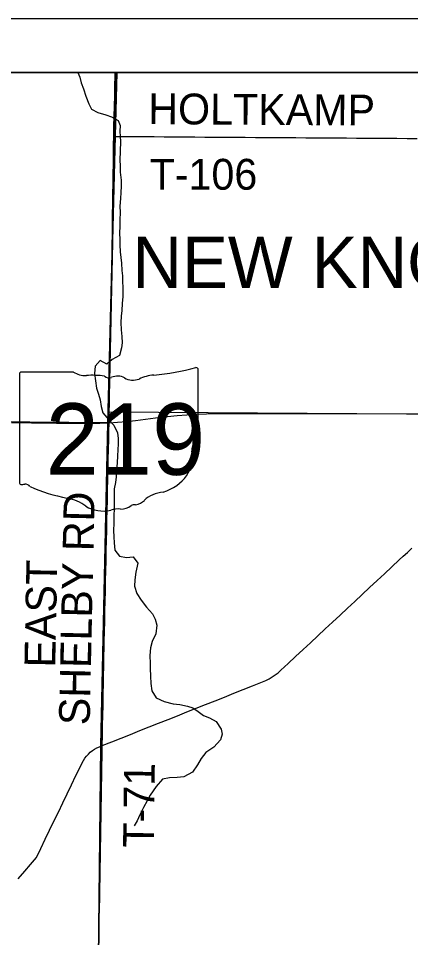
# Model space of a CAD drawing. Extents: x -11.1 to 34, y -3.9 to 22.
# Drawn here: x 7.271 to 7.994, y 19.305 to 21 of the extents above; entities that cross this region are included whole.
import ezdxf

# ---------------------------------------------------------------- set-up
doc = ezdxf.new("R2010")
doc.units = 0
for name, color, linetype in [('GM_X_Corporation', 7, 'Continuous'), ('GM_X_Corporation_Text', 7, 'Continuous'), ('GM_X_County_Road', 7, 'Continuous'), ('GM_X_Minor_River', 7, 'Continuous'), ('GM_X_State_Location', 7, 'Continuous'), ('GM_X_State_Route', 7, 'Continuous'), ('GM_X_State_Shield', 7, 'Continuous'), ('GM_X_Township_Road', 7, 'Continuous'), ('GM_X_Township_Road_Text', 7, 'Continuous'), ('SH_Data', 7, 'Continuous')]:
    doc.layers.add(name, color=color, linetype=linetype)

msp = doc.modelspace()

# ---------------------------------------------------------------- linework, layer by layer
at = {"layer": 'GM_X_Corporation'}
for points in [[(8.9, 19.2515), (8.9, 20.9), (2.1, 20.9)], [(7.4185, 19.2665), (7.4229, 19.6584), (7.436, 20.2539), (7.4494, 20.7828), (7.452, 20.9), (2.1, 20.9)], [(8.9, 19.2515), (8.9, 20.9), (7.452, 20.9), (7.4494, 20.7828), (7.436, 20.2539), (7.4229, 19.6584), (7.4185, 19.2665)]]:
    msp.add_lwpolyline(points, dxfattribs=at)
for points in [[(7.4509, 20.9), (6.4389, 20.9), (6.4249, 20.2637), (7.4361, 20.2547), (7.4373, 20.2744)], [(8.6363, 20.9), (7.4509, 20.9), (7.4373, 20.2744), (8.6259, 20.2667)]]:
    msp.add_lwpolyline(points, close=True, dxfattribs=at)
at = {"layer": 'GM_X_County_Road'}
for points in [[(7.4255, 19.659), (7.4428, 19.6659), (7.4601, 19.6728), (7.4774, 19.6797), (7.4947, 19.6866), (7.5121, 19.6935), (7.5294, 19.7004), (7.5467, 19.7073), (7.564, 19.7141), (7.5813, 19.721), (7.5987, 19.7279), (7.616, 19.7348), (7.6333, 19.7417), (7.6506, 19.7486), (7.6679, 19.7555), (7.6852, 19.7624), (7.7026, 19.7693), (7.7117, 19.7729), (7.7208, 19.7765), (7.7269, 19.7792), (7.7329, 19.7823), (7.7387, 19.7857), (7.7442, 19.7894), (7.7495, 19.7935), (7.7546, 19.798), (7.7682, 19.8107), (7.7819, 19.8234), (7.7955, 19.8361), (7.8091, 19.8488), (7.8228, 19.8615), (7.8364, 19.8742), (7.8501, 19.8869), (7.8637, 19.8996), (7.8773, 19.9123), (7.891, 19.925), (7.9046, 19.9378), (7.9182, 19.9505), (7.9319, 19.9632), (7.9455, 19.9759), (7.9592, 19.9886), (7.9728, 20.0013), (7.9803, 20.0083), (7.9878, 20.0153), (7.9961, 20.0229)], [(7.2703, 19.4133), (7.2824, 19.4275), (7.2932, 19.44), (7.3039, 19.4526), (7.3121, 19.4694), (7.3202, 19.4862), (7.3283, 19.5029), (7.3364, 19.5197), (7.3445, 19.5365), (7.3527, 19.5533), (7.3608, 19.5701), (7.3689, 19.5868), (7.377, 19.6036), (7.3828, 19.6155), (7.3885, 19.6275), (7.3909, 19.6318), (7.3935, 19.6359), (7.3965, 19.6398), (7.3998, 19.6434), (7.4034, 19.6468), (7.4073, 19.6498), (7.4114, 19.6525), (7.4157, 19.6549), (7.4202, 19.6569), (7.4255, 19.659)]]:
    msp.add_lwpolyline(points, dxfattribs=at)
at = {"layer": 'GM_X_Minor_River'}
for points in [[(7.3807, 20.9), (7.384, 20.8916), (7.3868, 20.8813), (7.3907, 20.8702), (7.395, 20.8568), (7.4004, 20.8426), (7.4058, 20.8327), (7.4175, 20.8267), (7.4318, 20.8222), (7.4427, 20.8182), (7.4547, 20.8119), (7.4583, 20.8023), (7.4581, 20.7921), (7.4586, 20.7822), (7.4588, 20.7727), (7.4581, 20.7382), (7.4582, 20.7287), (7.4587, 20.7166), (7.4603, 20.7017), (7.4604, 20.6907), (7.4598, 20.679), (7.4592, 20.6676), (7.4581, 20.654), (7.4582, 20.6418), (7.458, 20.6282), (7.4581, 20.6172), (7.4574, 20.6031), (7.4576, 20.5929), (7.4581, 20.5823), (7.4586, 20.5694)], [(7.4586, 20.5694), (7.4609, 20.5485), (7.4617, 20.5352), (7.4626, 20.5253), (7.463, 20.5143), (7.4635, 20.5044), (7.4631, 20.4874), (7.462, 20.4745), (7.4613, 20.4612), (7.4602, 20.4506), (7.4599, 20.4392), (7.4603, 20.4256), (7.4615, 20.4134), (7.462, 20.402), (7.4609, 20.3922), (7.4572, 20.3786), (7.4437, 20.371), (7.4336, 20.3625), (7.4213, 20.3693), (7.4126, 20.3589), (7.4111, 20.3449), (7.4127, 20.3316), (7.415, 20.3182), (7.4185, 20.3071), (7.4216, 20.2968), (7.4236, 20.2846), (7.4267, 20.2728), (7.4373, 20.26), (7.4465, 20.2498), (7.4534, 20.236), (7.4546, 20.225), (7.4547, 20.2155), (7.4534, 20.1935), (7.4527, 20.1806), (7.4519, 20.167), (7.4509, 20.1549), (7.4498, 20.1439), (7.4476, 20.1326), (7.4473, 20.1197), (7.4471, 20.1003), (7.4466, 20.0787), (7.4467, 20.0692), (7.4463, 20.0559), (7.4468, 20.0438), (7.4473, 20.0328), (7.4484, 20.0195), (7.4572, 20.0082), (7.4704, 20.006), (7.4826, 20.0072), (7.4907, 19.9956), (7.4876, 19.979), (7.4853, 19.9646), (7.485, 19.9528), (7.4892, 19.9395), (7.4972, 19.9271), (7.5067, 19.9143), (7.5178, 19.9019), (7.5232, 19.8923), (7.5263, 19.8808), (7.5244, 19.8649), (7.5176, 19.8511), (7.5146, 19.8394), (7.5131, 19.8254), (7.5138, 19.8105), (7.5136, 19.8011), (7.5143, 19.787), (7.5151, 19.7737), (7.517, 19.76), (7.5247, 19.7469), (7.5397, 19.7401), (7.5559, 19.7362), (7.5687, 19.7351), (7.5823, 19.7317), (7.5925, 19.7288), (7.6025, 19.7217), (7.6122, 19.7143), (7.6231, 19.7102), (7.6354, 19.7034), (7.6446, 19.6895), (7.6462, 19.68), (7.6433, 19.6694), (7.6308, 19.6561), (7.6161, 19.6462), (7.6078, 19.6351), (7.6011, 19.6235), (7.5916, 19.6101), (7.5758, 19.6017), (7.5633, 19.6002), (7.5492, 19.5998), (7.5366, 19.5971), (7.5245, 19.5837), (7.5135, 19.5677), (7.5079, 19.5572), (7.5015, 19.5449), (7.4947, 19.5314), (7.4895, 19.5205), (7.4843, 19.5108)]]:
    msp.add_lwpolyline(points, dxfattribs=at)
at = {"layer": 'GM_X_State_Route'}
msp.add_line((7.6667, 20.2711), (8.0333, 20.2706), dxfattribs=at)
for points in [[(7.438, 20.2543), (7.4538, 20.2554), (7.4702, 20.2568), (7.4865, 20.2586), (7.505, 20.2608), (7.5235, 20.2631), (7.5345, 20.2644), (7.5454, 20.2658), (7.5634, 20.2677), (7.5814, 20.2692), (7.5995, 20.2703), (7.6175, 20.271)], [(7.6175, 20.271), (7.6356, 20.2712), (7.6667, 20.2711)], [(7.2579, 20.2549), (7.2766, 20.2546), (7.2952, 20.2544), (7.3138, 20.2542), (7.3187, 20.2541)], [(7.3187, 20.2541), (7.3276, 20.254), (7.3413, 20.2538), (7.36, 20.2536), (7.3741, 20.2534), (7.3882, 20.2533), (7.4046, 20.2534), (7.421, 20.2536), (7.438, 20.2543)]]:
    msp.add_lwpolyline(points, dxfattribs=at)
at = {"layer": 'GM_X_State_Shield'}
for p, q in [((7.2726, 20.3443), (7.2726, 20.1441)), ((7.3724, 20.3477), (7.2759, 20.3477)), ((7.6022, 20.248), (7.6022, 20.3527)), ((7.6022, 20.248), (7.6022, 20.248))]:
    msp.add_line(p, q, dxfattribs=at)
for centre, major_axis, start_param, end_param in [((7.2764, 20.3447), (0.00382, 0), 1.712693, 3.28349), ((7.3954, 20.3709), (0.037, 0), 4.042523, 4.731795), ((7.4077, 20.2354), (0.133, 0), 1.404758, 1.657858), ((7.4378, 20.3457), (0.0107, 0), 3.836095, 5.185415), ((7.4535, 20.3226), (0.0222, 0), 0.950623, 2.079405), ((7.5294, 20.2866), (0.0703, 0), 1.699011, 2.107814), ((7.4848, 20.6205), (0.3495, 0), 4.814394, 5.042369), ((7.5985, 20.3531), (0.00367, 0), 6.141152, 7.989035), ((7.4822, 20.3543), (0.0267, 0), 4.081561, 5.145723), ((7.6014, 20.2403), (0.00568, 0), 1.883978, 3.671073), ((7.5983, 20.2476), (0.00393, 0), 5.05454, 6.418171), ((7.5652, 20.2271), (0.0341, 0), 5.934695, 6.695948), ((7.6153, 20.2042), (0.0248, 0), 2.387724, 3.262537), ((7.5044, 20.1909), (0.0874, 0), 5.101752, 6.440018), ((7.2764, 20.1437), (0.00385, 0), 3.00124, 4.508301), ((7.277, 20.1642), (0.0294, 0), 4.665946, 4.897461), ((7.283, 20.1326), (0.0106, 0), 0.519207, 1.627899), ((7.4169, 20.3124), (0.2524, 0), 4.195997, 4.488961), ((7.5412, 20.088), (0.0479, 0), 1.647645, 2.488434), ((7.3416, 20.0542), (0.079, 0), 0.823519, 1.323587), ((7.4838, 20.0972), (0.00752, 0), 1.147584, 2.315152), ((7.4806, 20.1247), (0.0282, 0), 4.937069, 5.64225), ((7.427, 20.1316), (0.0501, 0), 4.026481, 4.996735), ((7.456, 20.0624), (0.0412, 0), 1.495662, 1.94098), ((7.4596, 20.1166), (0.0267, 0), 4.691044, 5.507374)]:
    msp.add_ellipse(centre, major_axis=major_axis, ratio=0.8, start_param=start_param, end_param=end_param, dxfattribs=at)
at = {"layer": 'GM_X_Township_Road'}
for points in [[(7.4466, 20.7824), (7.447, 20.801), (7.4475, 20.8196), (7.4479, 20.8383), (7.4483, 20.8569), (7.4488, 20.8755), (7.4492, 20.8942), (7.4493, 20.9)], [(7.4373, 20.2256), (7.4376, 20.239), (7.438, 20.2543), (7.4383, 20.2729), (7.4386, 20.2916), (7.4389, 20.3102), (7.4392, 20.3289), (7.4395, 20.3475), (7.4398, 20.3617), (7.44, 20.3758), (7.4404, 20.3944), (7.4408, 20.4131), (7.4411, 20.4317), (7.4415, 20.4503), (7.4419, 20.469), (7.4422, 20.4876), (7.4426, 20.5062), (7.4428, 20.5166), (7.443, 20.5269), (7.4433, 20.5456), (7.4436, 20.5642), (7.4438, 20.5828), (7.4441, 20.6015), (7.4443, 20.6201), (7.4446, 20.6388), (7.4449, 20.6574), (7.4451, 20.676), (7.4454, 20.6947), (7.4457, 20.7133), (7.4459, 20.732), (7.4462, 20.7506), (7.4464, 20.7665), (7.4466, 20.7824)], [(7.4466, 20.7824), (7.4653, 20.7822), (7.4839, 20.7821), (7.5025, 20.782), (7.5212, 20.7819), (7.5398, 20.7817), (7.5585, 20.7816), (7.5771, 20.7815), (7.5958, 20.7814), (7.6144, 20.7812), (7.633, 20.7811), (7.6517, 20.781), (7.6703, 20.7808), (7.689, 20.7807), (7.7076, 20.7806), (7.7262, 20.7805), (7.7449, 20.7803), (7.7635, 20.7802), (7.7822, 20.7801), (7.8008, 20.78), (7.8194, 20.7798), (7.8381, 20.7797), (7.8567, 20.7796), (7.8754, 20.7794), (7.894, 20.7793), (7.9127, 20.7792), (7.9313, 20.7791), (7.9499, 20.7789), (7.9686, 20.7788), (7.9872, 20.7787), (8.0059, 20.7786)], [(7.4194, 19.3033), (7.4197, 19.3219), (7.42, 19.3405), (7.4204, 19.3592), (7.4207, 19.3778), (7.421, 19.3965), (7.4213, 19.4151), (7.4216, 19.4338), (7.4219, 19.4524), (7.4223, 19.471), (7.4226, 19.4897), (7.4229, 19.5083), (7.4232, 19.527), (7.4235, 19.5456), (7.4238, 19.5642), (7.4242, 19.5829), (7.4245, 19.6015), (7.4248, 19.6202), (7.4251, 19.6388), (7.4253, 19.6489), (7.4255, 19.659), (7.4258, 19.6777), (7.4261, 19.6963), (7.4265, 19.7149), (7.4268, 19.7323), (7.4271, 19.7496), (7.4273, 19.7591), (7.4275, 19.7687), (7.4279, 19.7873), (7.4282, 19.8059), (7.4286, 19.8246), (7.4289, 19.8378), (7.4292, 19.851), (7.4296, 19.8696), (7.43, 19.8883), (7.4304, 19.9069), (7.4308, 19.9256), (7.4312, 19.9442), (7.4316, 19.9628), (7.432, 19.9815), (7.4324, 20.0001), (7.4328, 20.0187), (7.4332, 20.0374), (7.4336, 20.056), (7.434, 20.0746), (7.4344, 20.0933), (7.4349, 20.1119), (7.4353, 20.1305), (7.4357, 20.1492), (7.4361, 20.1678), (7.4365, 20.1864), (7.4369, 20.2051), (7.4373, 20.2237), (7.4373, 20.2256)]]:
    msp.add_lwpolyline(points, dxfattribs=at)
at = {"layer": 'SH_Data'}
for p, q in [((2, 21), (9, 21)), ((2.1, 20.9), (8.9, 20.9))]:
    msp.add_line(p, q, dxfattribs=at)

# ---------------------------------------------------------------- texts
at = {"layer": 'GM_X_Corporation_Text'}
msp.add_text('NEW KNOXVILLE', height=0.094697, rotation=0, dxfattribs=at).set_placement((7.481, 20.503))
at = {"layer": 'GM_X_State_Location'}
for s in ['s', 'r']:
    msp.add_text(s, height=0.000189, dxfattribs=at).set_placement((7.4337, 20.2309))
msp.add_text('219', height=0.000189, rotation=0, dxfattribs=at).set_placement((7.3668, 20.2171))
at = {"layer": 'GM_X_State_Shield'}
msp.add_text('219', height=0.13184, dxfattribs=at).set_placement((7.3211, 20.1583))
at = {"layer": 'GM_X_Township_Road_Text'}
for s, rotation, p in [('HOLTKAMP', 359.6294, (7.5101, 20.805)), ('T-106', 0, (7.5127, 20.6841)), ('SHELBY RD', 88.7575, (7.4022, 19.6961)), ('EAST', 88.8978, (7.3387, 19.8026)), ('T-71', 89.2924, (7.5205, 19.4706))]:
    msp.add_text(s, height=0.05682, rotation=rotation, dxfattribs=at).set_placement(p)

doc.saveas('drawing.dxf')
